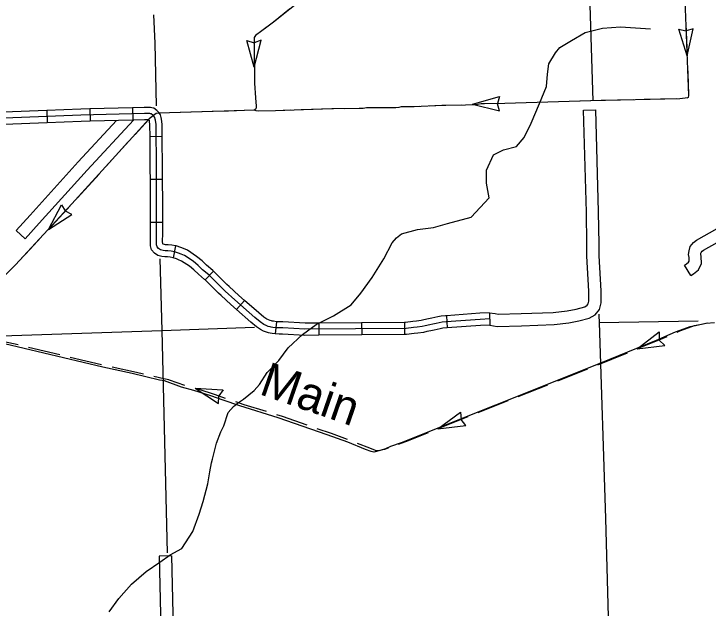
# Model space of a CAD drawing. Extents: x 1164457 to 1439835, y 1590918 to 1773502.
# Drawn here: x 1259097 to 1267639, y 1641151 to 1648464 of the extents above; entities that cross this region are included whole.
import ezdxf

# ---------------------------------------------------------------- set-up
doc = ezdxf.new("R2010")
doc.units = 0
for name, color, linetype in [('Level 32', 7, 'Continuous'), ('Level 4', 7, 'Continuous'), ('Level 43', 7, 'Continuous'), ('Level 46', 7, 'Continuous'), ('Level 5', 7, 'Continuous')]:
    doc.layers.add(name, color=color, linetype=linetype)

msp = doc.modelspace()

# ---------------------------------------------------------------- linework, layer by layer
at = {"layer": 'Level 32'}
for p, q in [((1259501.4, 1647274.6), (1259507.2, 1647124.7)), ((1260030, 1647293.6), (1260033.9, 1647143.6)), ((1260557.8, 1647307.4), (1260561.8, 1647157.5)), ((1260922.9, 1646953.1), (1260772.9, 1646952.1)), ((1260926.7, 1646425.2), (1260776.7, 1646424)), ((1260928.9, 1645896.6), (1260778.9, 1645896.6)), ((1261084.2, 1645610.3), (1261057.4, 1645462.7)), ((1261555.3, 1645296.2), (1261449.7, 1645189.7)), ((1261936.6, 1644937.9), (1261837.8, 1644825.1)), ((1264948.5, 1644784.3), (1264954.3, 1644634.4)), ((1264419.1, 1644749.8), (1264430, 1644600.2)), ((1262329.6, 1644676), (1262311.7, 1644527.1)), ((1262847.6, 1644659), (1262848.7, 1644509)), ((1263375.6, 1644662.8), (1263376.7, 1644512.8)), ((1263903.6, 1644666.6), (1263904.6, 1644516.6))]:
    msp.add_line(p, q, dxfattribs=at)
for points in [[(1259501.4, 1647274.6), (1258973.8, 1647254.3)], [(1260030, 1647293.6), (1259919.7, 1647290.7), (1259501.4, 1647274.6)], [(1260557.8, 1647307.4), (1260030, 1647293.6)], [(1260922.9, 1646953.1), (1260921.8, 1647108.1), (1260913.3, 1647170.2), (1260909.4, 1647188.7), (1260899.4, 1647219.6), (1260880.5, 1647249), (1260857.8, 1647275), (1260817.4, 1647302.3), (1260795.7, 1647307.2), (1260778.4, 1647311.2), (1260753.2, 1647311.2), (1260702.1, 1647311.2), (1260557.8, 1647307.4)], [(1264951.4, 1644709.4), (1264832.5, 1644704.7), (1264416.2, 1644674.4), (1264364.9, 1644668.5), (1264328.7, 1644661.5), (1264291.4, 1644653.4), (1264253, 1644646.4), (1264213.3, 1644637), (1264159.6, 1644626.6), (1264121.7, 1644616.7), (1264058.9, 1644608), (1264015.3, 1644604.8), (1263923, 1644591.8), (1262677.7, 1644582.8), (1262405.4, 1644598.4), (1262361.8, 1644599), (1262325.8, 1644601), (1262283.2, 1644606.1), (1262263.4, 1644608.4), (1262248.9, 1644611.9), (1262227.1, 1644618.3), (1262199.5, 1644627.9), (1262170.6, 1644642.7), (1262127, 1644672.2), (1262062.5, 1644728), (1261816.2, 1644943.6), (1261697.1, 1645053.2), (1261666.9, 1645080.1), (1261494.8, 1645250.5), (1261418.3, 1645315.1), (1261363.1, 1645369), (1261301.6, 1645419.1), (1261195.1, 1645488.4), (1261154, 1645507.6), (1261123.8, 1645520.4), (1261074.5, 1645535.9), (1261032.2, 1645543.6), (1260992.4, 1645547.4), (1260959, 1645547.4), (1260933.4, 1645551.3), (1260901.3, 1645560.2), (1260878.2, 1645576.9), (1260860.3, 1645596.2), (1260853.9, 1645621.8), (1260851.3, 1645662.9), (1260853.9, 1645761.7), (1260853.9, 1646144.1), (1260850.7, 1646553.5), (1260846.8, 1647102.8), (1260839.4, 1647157.4), (1260836.8, 1647169.3), (1260831.1, 1647187.2), (1260820.3, 1647203.8), (1260807.7, 1647218.3), (1260787, 1647232.3), (1260778.9, 1647234.1), (1260769.8, 1647236.2), (1260753.2, 1647236.2), (1260703.1, 1647236.2), (1259922.1, 1647215.7), (1258139.5, 1647147.3)], [(1259507.2, 1647124.7), (1258979.6, 1647104.5)], [(1260033.9, 1647143.6), (1259924.6, 1647140.7), (1259507.2, 1647124.7)], [(1260561.8, 1647157.5), (1260033.9, 1647143.6)], [(1260772.9, 1646952.1), (1260771.8, 1647097.4), (1260765.4, 1647144.6), (1260764.3, 1647150), (1260762.7, 1647154.7), (1260760.2, 1647158.6), (1260758, 1647161.2), (1260753.2, 1647161.2), (1260704.1, 1647161.2), (1260561.8, 1647157.5)], [(1260776.7, 1646424), (1260775.7, 1646553), (1260772.9, 1646952.1)], [(1260926.7, 1646425.2), (1260925.6, 1646554.1), (1260922.9, 1646953.1)], [(1260778.9, 1645896.6), (1260778.9, 1646143.8), (1260776.7, 1646424)], [(1260928.9, 1645896.6), (1260928.9, 1646144.4), (1260926.7, 1646425.2)], [(1261057.4, 1645462.7), (1261021.8, 1645469.2), (1260988.8, 1645472.4), (1260953.5, 1645472.4), (1260917.7, 1645477.8), (1260868.2, 1645491.6), (1260828.4, 1645520.4), (1260792.2, 1645559.2), (1260779.4, 1645610.3), (1260776.2, 1645661.5), (1260778.9, 1645762.7), (1260778.9, 1645896.6)], [(1261084.2, 1645610.3), (1261042.5, 1645617.9), (1260996, 1645622.4), (1260964.6, 1645622.4), (1260949.1, 1645624.7), (1260934.4, 1645628.9), (1260928.3, 1645633.3), (1260928.3, 1645633.4), (1260926.4, 1645664.3), (1260928.9, 1645760.7), (1260928.9, 1645896.6)], [(1261555.3, 1645296.2), (1261545.5, 1645305.9), (1261468.8, 1645370.7), (1261413.1, 1645425.1), (1261345.8, 1645479.8), (1261231.6, 1645554.1), (1261184.6, 1645576.1), (1261149.7, 1645590.9), (1261092.5, 1645608.8), (1261084.3, 1645610.3)], [(1261449.7, 1645189.7), (1261444.2, 1645195.2), (1261367.8, 1645259.6), (1261313.2, 1645313), (1261257.3, 1645358.4), (1261158.5, 1645422.7), (1261123.5, 1645439.1), (1261098, 1645449.9), (1261056.5, 1645462.9), (1261057.4, 1645462.7)], [(1261936.6, 1644937.9), (1261866.3, 1644999.4), (1261747.4, 1645108.9), (1261718.3, 1645134.8), (1261555.3, 1645296.2)], [(1261837.8, 1644825.1), (1261766.1, 1644887.8), (1261646.8, 1644997.6), (1261615.6, 1645025.4), (1261449.7, 1645189.7)], [(1262329.6, 1644676), (1262291.9, 1644680.6), (1262276.5, 1644682.3), (1262268.3, 1644684.3), (1262250, 1644689.7), (1262229, 1644697), (1262208.8, 1644707.4), (1262172.7, 1644731.8), (1262111.8, 1644784.6), (1261936.6, 1644937.9)], [(1262311.7, 1644527.1), (1262274.4, 1644531.6), (1262250.3, 1644534.4), (1262229.5, 1644539.4), (1262204.1, 1644546.9), (1262169.9, 1644558.8), (1262132.4, 1644578), (1262081.3, 1644612.6), (1262013.3, 1644671.4), (1261837.8, 1644825.1)], [(1264948.5, 1644784.3), (1264828.3, 1644779.6), (1264419.1, 1644749.8)], [(1264419.1, 1644749.8), (1264409.2, 1644749.1), (1264353.5, 1644742.7), (1264313.6, 1644735), (1264276.7, 1644726.9), (1264237.7, 1644719.8), (1264197.6, 1644710.4), (1264143, 1644699.8), (1264107, 1644690.4), (1264051, 1644682.6), (1264007.3, 1644679.4), (1263917.4, 1644666.7), (1263903.6, 1644666.6)], [(1262847.6, 1644659), (1262679.5, 1644657.8), (1262408.1, 1644673.4), (1262364.3, 1644674), (1262332.3, 1644675.7), (1262329.6, 1644676)], [(1263375.6, 1644662.8), (1262847.6, 1644659)], [(1263903.6, 1644666.6), (1263375.6, 1644662.8)], [(1264954.3, 1644634.4), (1264836.7, 1644629.8), (1264430, 1644600.2)], [(1262848.7, 1644509), (1262675.8, 1644507.8), (1262402.7, 1644523.4), (1262359.2, 1644524.1), (1262319.3, 1644526.2), (1262311.7, 1644527.1)], [(1264430, 1644600.2), (1264423.1, 1644599.7), (1264376.3, 1644594.3), (1264343.9, 1644588.1), (1264306.2, 1644579.8), (1264268.3, 1644572.9), (1264229, 1644563.7), (1264176.3, 1644553.5), (1264136.4, 1644543), (1264066.9, 1644533.4), (1264023.3, 1644530.2), (1263928.5, 1644516.8), (1263904.6, 1644516.6)], [(1263376.7, 1644512.8), (1262848.7, 1644509)], [(1263904.6, 1644516.6), (1263376.7, 1644512.8)]]:
    msp.add_lwpolyline(points, dxfattribs=at)
at = {"layer": 'Level 4'}
for points in [[(1266142.8, 1649886.1), (1266221.2, 1647393.8)], [(1266293.9, 1644766.9), (1266293.8, 1644750.7), (1266296.7, 1644666.4), (1266377.8, 1642254.8), (1266408.2, 1641042)]]:
    msp.add_lwpolyline(points, dxfattribs=at)
at = {"layer": 'Level 43'}
for p, q in [((1267379.2, 1647947), (1267277.6, 1648274.9)), ((1267277.6, 1648274.9), (1267366.7, 1648254.6)), ((1267455.2, 1648281.7), (1267367.9, 1648254.7)), ((1267379.2, 1647947), (1267455.2, 1648281.7)), ((1262055.7, 1647806.8), (1261962.6, 1648137.1)), ((1261962.6, 1648137.1), (1262053.6, 1648109.4)), ((1262139.8, 1648139.5), (1262053.6, 1648109.4)), ((1262055.7, 1647806.8), (1262139.8, 1648139.5)), ((1264741.2, 1647354.1), (1265071.1, 1647448.7)), ((1265071.1, 1647448.7), (1265049, 1647360)), ((1264741.2, 1647354.1), (1265074.2, 1647271.1)), ((1265074.2, 1647271.1), (1265049.1, 1647358.8)), ((1259521.2, 1645812.4), (1259681.4, 1646115.9)), ((1259681.4, 1646115.9), (1259730.1, 1646038.5)), ((1259521.2, 1645812.4), (1259811.7, 1645995.1)), ((1259811.7, 1645995.1), (1259730.9, 1646037.7)), ((1266765.9, 1644340.1), (1267037.4, 1644550)), ((1267037.4, 1644550), (1267035.3, 1644449.8)), ((1267106.4, 1644383.1), (1267035.3, 1644449.8)), ((1266765.9, 1644340.1), (1267106.4, 1644383.1)), ((1261326.7, 1643856.2), (1261614.8, 1643669.7)), ((1261326.7, 1643856.2), (1261669.5, 1643838.8)), ((1261613.1, 1643669.1), (1261619.2, 1643760.2)), ((1261670.5, 1643837.3), (1261619.6, 1643761.4)), ((1264315.3, 1643358.3), (1264590.3, 1643563.7)), ((1264590.3, 1643563.7), (1264601, 1643472.9)), ((1264656.1, 1643398.7), (1264601.5, 1643471.8)), ((1264315.3, 1643358.3), (1264656.1, 1643398.7))]:
    msp.add_line(p, q, dxfattribs=at)
for points in [[(1272592.9, 1648861.1), (1271287.2, 1648800.3), (1270691.8, 1648795.3), (1270618.4, 1648796.9), (1270255.3, 1648783.4), (1269749.3, 1648763.2), (1269252.7, 1648756.4), (1268790, 1648771.6), (1268651.5, 1648776.7), (1268601.7, 1648768.2), (1268562.9, 1648761.4), (1268453.3, 1648757.6), (1268422.3, 1648752.5), (1267954.2, 1648738.3), (1267472.5, 1648731.1), (1267379.6, 1648724.3), (1267367.8, 1648715.9), (1267357.6, 1648702.3), (1267352.6, 1648683.8), (1267352.6, 1648634.8), (1267398.2, 1647458.7), (1267392.2, 1647436.6), (1267387.2, 1647429), (1267355.9, 1647425.6)], [(1262674.4, 1648668.7), (1262291.2, 1648363.4), (1262150, 1648254.1), (1262070.8, 1648196), (1262052.8, 1648172), (1262052.8, 1648156.9), (1262057.3, 1647611.1), (1262070.7, 1647432), (1262077.1, 1647330.3), (1262077.8, 1647315.5), (1262074.6, 1647296.3), (1262065, 1647286), (1262055.2, 1647277.1), (1261683.3, 1647264.9), (1260878.1, 1647242.7), (1260847.5, 1647238.3), (1260762.1, 1647170.8), (1259812.3, 1646126.4), (1259117.3, 1645376.8), (1258984.1, 1645244.4)], [(1262488.2, 1648520.4), (1262291.2, 1648363.4), (1262177.3, 1648275.3)], [(1263505.9, 1645218.8), (1263650.6, 1645450.1), (1263750.8, 1645646.4), (1263804.8, 1645709.6), (1263868.3, 1645755.9), (1264062.8, 1645808.6), (1264261.6, 1645836.3), (1264433.6, 1645884.9), (1264723.3, 1645962.7), (1264946.1, 1646201.9), (1264913.7, 1646380.3), (1264913.7, 1646542.5), (1264999.1, 1646728.9), (1265123.4, 1646790.9), (1265283.2, 1646830.2), (1265376.6, 1646941), (1265462.6, 1647118.1), (1265563.5, 1647361.6), (1265649.5, 1647570.8), (1265661.8, 1647723.3), (1265679, 1647848.8), (1265760.2, 1647984.1), (1265813.2, 1648050.7), (1265959.1, 1648135.9), (1266125.3, 1648233.2), (1266337.9, 1648286.7), (1266560.4, 1648305.5), (1266931.6, 1648281.9)], [(1267363.9, 1648342.7), (1267379.2, 1647947)], [(1262071.4, 1648196.4), (1262070.8, 1648196), (1262052.8, 1648172), (1262052.8, 1648156.9), (1262055.7, 1647806.8)], [(1267384.4, 1647815.1), (1267392, 1647617.3)], [(1262056.8, 1647674.8), (1262057.3, 1647611.1), (1262070.7, 1647432), (1262077.1, 1647330.3), (1262077.8, 1647315.5), (1262074.6, 1647296.3), (1262065, 1647286), (1262063.2, 1647284.3)], [(1267392, 1647617.3), (1267398.2, 1647458.7), (1267392.2, 1647436.6), (1267387.2, 1647429), (1267380, 1647428.2)], [(1267355.9, 1647425.6), (1267292.6, 1647420.5), (1266195.2, 1647393), (1265136.8, 1647361), (1264886.3, 1647356.6), (1264845.6, 1647356.6), (1264803.4, 1647349.4), (1264768.5, 1647345), (1264653.7, 1647340.6), (1264362.9, 1647334.8), (1264024.1, 1647320.3), (1263860.7, 1647318.8), (1263833.1, 1647313), (1263796.8, 1647308.6), (1263639.7, 1647308.6), (1263506, 1647308.6), (1263436.2, 1647307.2), (1263394, 1647301.4), (1263344.6, 1647298.5), (1263007.3, 1647294.1), (1262314.7, 1647270.8), (1262104.7, 1647267.3), (1262079, 1647271.8), (1262055.2, 1647277.1)], [(1265137.2, 1647361), (1265136.8, 1647361), (1264886.3, 1647356.6), (1264845.6, 1647356.6), (1264803.4, 1647349.4), (1264768.5, 1647345), (1264742.1, 1647344)], [(1265664.9, 1647377), (1265269.1, 1647365)], [(1266192.7, 1647392.9), (1265796.9, 1647380.9)], [(1266720.5, 1647406.2), (1266324.6, 1647396.2)], [(1267248.3, 1647419.4), (1266852.5, 1647409.5)], [(1261736.1, 1647266.6), (1261683.3, 1647264.9), (1261538.2, 1647260.9)], [(1261934, 1647273.1), (1261736.1, 1647266.6)], [(1262500.2, 1647277.1), (1262314.7, 1647270.8), (1262104.7, 1647267.3), (1262104.4, 1647267.4)], [(1263027.9, 1647294.4), (1263007.3, 1647294.1), (1262632.2, 1647281.5)], [(1263555.4, 1647308.6), (1263506, 1647308.6), (1263436.2, 1647307.2), (1263394, 1647301.4), (1263344.6, 1647298.5), (1263159.9, 1647296.1)], [(1264082.5, 1647322.8), (1264024.1, 1647320.3), (1263860.7, 1647318.8), (1263833.1, 1647313), (1263796.8, 1647308.6), (1263687.4, 1647308.6)], [(1264412.2, 1647335.8), (1264362.9, 1647334.8), (1264214.4, 1647328.4)], [(1264610.2, 1647339.8), (1264412.2, 1647335.8)], [(1261406.2, 1647257.2), (1261010.4, 1647246.3)], [(1260753.4, 1647161.2), (1260589.9, 1646981.5)], [(1260501.1, 1646883.8), (1260234.7, 1646590.8)], [(1260145.9, 1646493.2), (1259879.4, 1646200.2)], [(1259790.4, 1646102.8), (1259521.2, 1645812.4)], [(1259431.4, 1645715.6), (1259296.8, 1645570.4)], [(1259296.8, 1645570.4), (1259162.2, 1645425.2)], [(1260267.7, 1641106.7), (1260386.7, 1641270.7), (1260545, 1641446.2), (1260723.9, 1641602.2), (1260893.9, 1641717.7), (1261021.3, 1641808.5), (1261162.5, 1641886.3), (1261297.7, 1642094.4), (1261378.8, 1642308.4), (1261428, 1642463.4), (1261482.1, 1642679.9), (1261509.1, 1642830), (1261526.9, 1642940.3), (1261541.7, 1642985.5), (1261590.2, 1643179.8), (1261641.7, 1643320), (1261681.8, 1643392.5), (1261732.3, 1643556.8), (1261798.1, 1643633.8), (1261859.9, 1643682.3), (1261922.2, 1643720.6), (1262052.5, 1643828.6), (1262119.8, 1643900.9), (1262212.8, 1644050), (1262358.6, 1644198.3), (1262470.7, 1644353.6), (1262649.9, 1644517.7), (1262814.7, 1644643.1), (1263029.4, 1644748.5), (1263247.4, 1644881.8), (1263364.9, 1645027.9), (1263505.9, 1645218.8), (1263505.9, 1645218.8)], [(1267717.9, 1644660.6), (1267613.9, 1644652), (1267557.4, 1644641.8), (1267481.8, 1644625.3), (1267415.2, 1644613), (1267336.7, 1644582.4), (1267234.9, 1644546.1), (1266998.8, 1644442.9), (1266181.7, 1644111.3), (1263863.1, 1643185.7), (1263732.2, 1643137.7), (1263669.8, 1643112.4), (1263605.7, 1643091.2), (1263527, 1643071.4), (1263491.6, 1643077.9), (1263424, 1643104.3), (1263204.5, 1643193), (1262951.5, 1643284.6), (1262347.4, 1643494.1), (1261877.1, 1643641), (1261673.6, 1643710.8), (1261522.5, 1643762.3), (1261313, 1643830), (1261157.9, 1643871.3), (1260948.7, 1643946.6), (1260888.5, 1643958), (1260554.1, 1644036.5), (1260191.5, 1644115.3), (1258981.1, 1644403.8)], [(1267630.5, 1644658.7), (1267610.8, 1644655.1), (1267535.2, 1644638.7), (1267468.7, 1644626.4), (1267390.2, 1644595.8), (1267288.4, 1644559.5), (1267252.9, 1644544)], [(1259148.6, 1644389.9), (1259034.6, 1644417.1), (1258854.5, 1644452.1), (1258769.8, 1644469.6), (1258761, 1644470.6)], [(1267132, 1644491.1), (1267052.3, 1644456.3), (1266949.4, 1644414.5)], [(1259662.2, 1644267.5), (1259277, 1644359.3)], [(1266949.4, 1644414.5), (1266765.9, 1644340.1)], [(1266643.6, 1644290.4), (1266276.7, 1644141.5)], [(1260175.8, 1644145.1), (1259790.6, 1644236.9)], [(1260691.1, 1644030.3), (1260607.5, 1644049.9), (1260304.5, 1644115.7)], [(1266154.2, 1644092.4), (1265786.4, 1643945.5)], [(1261012.6, 1643956.2), (1261002.2, 1643959.9), (1260941.9, 1643971.4), (1260819.6, 1644000.1)], [(1261198.9, 1643889.2), (1261012.6, 1643956.2)], [(1261702.8, 1643732.4), (1261575.9, 1643775.7), (1261366.5, 1643843.4), (1261326.1, 1643854.1)], [(1265663.8, 1643896.6), (1265296.1, 1643749.8)], [(1262204.8, 1643568.7), (1261930.6, 1643654.3), (1261827.7, 1643689.6)], [(1265173.5, 1643700.8), (1264805.7, 1643554)], [(1262705.6, 1643401.8), (1262400.9, 1643507.5), (1262330.8, 1643529.4)], [(1264683.1, 1643505.1), (1264315.3, 1643358.3)], [(1263203.5, 1643226.1), (1263005, 1643298), (1262830.4, 1643358.5)], [(1264192.7, 1643309.3), (1264008.8, 1643235.9)], [(1263700.6, 1643118.3), (1263659.2, 1643104.6), (1263580.4, 1643084.7), (1263545.1, 1643091.3), (1263477.5, 1643117.6), (1263326.7, 1643178.6)], [(1264008.8, 1643235.9), (1263916.5, 1643199.1), (1263823.9, 1643165.1)]]:
    msp.add_lwpolyline(points, dxfattribs=at)
at = {"layer": 'Level 46'}
for points in [[(1264948.5, 1644784.3), (1265018.7, 1644775.2), (1265055.5, 1644768.2), (1265338.1, 1644774.8), (1265732.7, 1644789.2), (1265903.5, 1644810.3), (1266013.8, 1644831.5), (1266120.3, 1644860.1), (1266151.4, 1644877.3), (1266164.1, 1644893.6), (1266172.6, 1644927.3), (1266172.6, 1645052.6), (1266148.1, 1645482.4), (1266146.7, 1645628.1), (1266142.3, 1646023), (1266106.4, 1647278.2), (1266256.3, 1647282.5)], [(1264954.3, 1644634.4), (1265043.2, 1644617.9), (1265342.6, 1644624.9), (1265744.7, 1644639.6), (1265926.8, 1644662.1), (1266047.4, 1644685.2), (1266177.1, 1644720), (1266250.7, 1644760.9), (1266301.9, 1644826.1), (1266322.6, 1644908.8), (1266322.6, 1645056.9), (1266298.1, 1645487.5), (1266296.6, 1645629.7), (1266292.3, 1646026), (1266256.3, 1647282.5)], [(1260569.9, 1647157.7), (1260000.4, 1646541.6), (1259410, 1645887.9), (1259234.7, 1645696.4), (1259124, 1645797.7)], [(1260360.6, 1647152.2), (1259889.6, 1646642.8), (1259299, 1645988.8), (1259124, 1645797.7)], [(1267425.4, 1645244), (1267346.4, 1645371.6), (1267373.1, 1645388.1), (1267399.1, 1645408.9), (1267405.1, 1645422.1), (1267404.1, 1645464.9), (1267397.2, 1645504.7), (1267403.9, 1645549.4), (1267416.4, 1645599.4), (1267460.5, 1645650.2), (1267495, 1645680.6), (1267910.7, 1645911.9), (1268508.1, 1646225.9), (1268558.3, 1646260.1), (1268571.2, 1646277.4), (1268576.4, 1646290), (1268581, 1646342.5), (1268585.4, 1646438.5), (1268589.3, 1646483.7), (1268605.9, 1646528), (1268641.5, 1646571.8), (1268692.1, 1646600.4), (1268724.7, 1646608.9), (1268763.8, 1646618.7)], [(1267425.4, 1645244), (1267459.8, 1645265.3), (1267521, 1645314.3), (1267555.8, 1645391.4), (1267553.8, 1645479.5), (1267549.1, 1645506.5), (1267551.2, 1645520), (1267553.2, 1645528.2), (1267567.2, 1645544.3), (1267582.1, 1645557.5), (1267982.1, 1645780), (1268585.6, 1646097.2), (1268663.4, 1646150.2), (1268702.8, 1646202.8), (1268723.8, 1646254.2), (1268730.7, 1646332.5), (1268735.1, 1646428.6), (1268737, 1646450.2), (1268737.8, 1646452.5), (1268740, 1646455.2), (1268749, 1646460.2), (1268761.9, 1646463.6), (1268800.1, 1646473.1)], [(1261034.5, 1641793.2), (1260884.5, 1641789.6), (1260943.8, 1639290.5)], [(1261034.5, 1641793.2), (1261093.7, 1639295.7)]]:
    msp.add_lwpolyline(points, dxfattribs=at)
at = {"layer": 'Level 5'}
for points in [[(1260817, 1648453.5), (1260829.5, 1648103.1), (1260848.3, 1647332.1)], [(1260894.4, 1645448.6), (1260915.9, 1644568.1)], [(1266296.7, 1644666.4), (1267517.5, 1644686.3)], [(1258821.7, 1644499.3), (1260915.9, 1644568.1)], [(1260915.9, 1644568.1), (1262059.2, 1644606.9)], [(1260915.9, 1644568.1), (1260983.6, 1641830.4)]]:
    msp.add_lwpolyline(points, dxfattribs=at)

# ---------------------------------------------------------------- texts
at = {"layer": 'Level 43'}
msp.add_text('Main', height=422, rotation=340.85156, dxfattribs=at).set_placement((1262101.6, 1643788.5))

doc.saveas('drawing.dxf')
